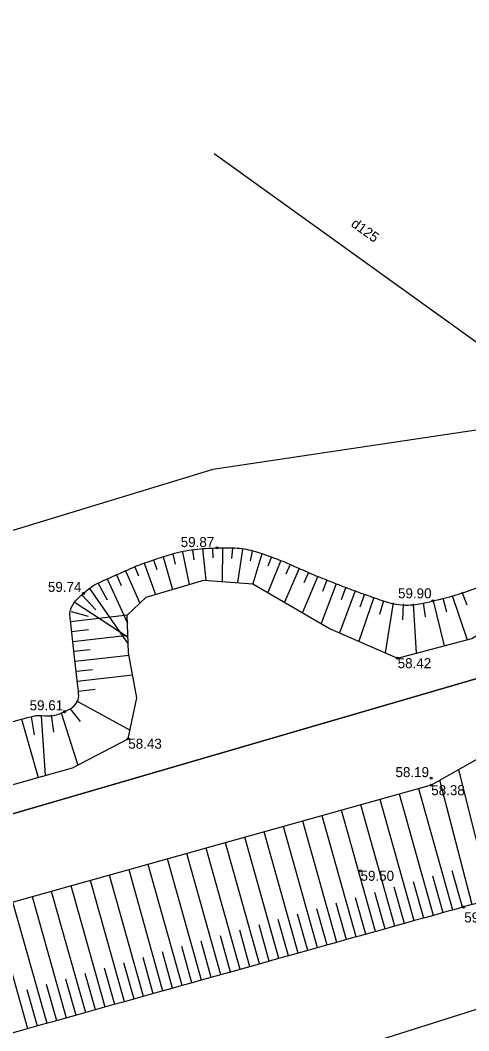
# Model space of a CAD drawing. Extents: x 616607 to 617499, y 408385 to 409695.
# Drawn here: x 616915.2 to 616937.6, y 408564.5 to 408614.9 of the extents above; entities that cross this region are included whole.
import ezdxf

# ---------------------------------------------------------------- set-up
doc = ezdxf.new("R2010")
doc.units = 0
for name, color, linetype in [('DREN_VADP_####_####_#', 7, 'Continuous'), ('DREN_VADP_####_TKST_#', 7, 'Continuous'), ('HIDG_GRAV_####_####_#', 7, 'Continuous'), ('RAMI_UZMR_####_####_#', 7, 'Continuous'), ('RELJ_AATZ_####_TKST_#', 7, 'Continuous'), ('RELJ_ELEM_####_####_#', 7, 'Continuous'), ('RELJ_NOGA_####_####_#', 7, 'Continuous'), ('ROBZ_IERR_####_####_#', 7, 'Continuous'), ('ROBZ_UZMR_####_####_#', 7, 'Continuous')]:
    doc.layers.add(name, color=color, linetype=linetype)

# ---------------------------------------------------------------- blocks, each defined once
blk = doc.blocks.new('PKT')
at = {"layer": 'RELJ_ELEM_####_####_#'}
blk.add_circle((0, 0), 0.05, dxfattribs=at)

msp = doc.modelspace()

# ---------------------------------------------------------------- linework, layer by layer
at = {"layer": 'DREN_VADP_####_####_#'}
msp.add_lwpolyline([(616944.351, 408594.236), (616924.897, 408608.204)], dxfattribs=at)
at = {"layer": 'HIDG_GRAV_####_####_#'}
for points in [[(616768.796, 408535.775), (616917.84, 408577.602), (616920.619, 408579.054), (616921.042, 408581.087), (616920.637, 408583.341), (616920.568, 408585.209), (616921.519, 408586.112), (616924.38, 408586.959), (616926.829, 408586.782), (616930.695, 408584.537), (616934.052, 408583.069), (616937.754, 408584.05), (616942.21, 408586.817), (616945.351, 408589.192), (616956.708, 408604.801)], [(616957.621, 408604.01), (616947.332, 408588.16), (616947.6, 408585.931), (616945.208, 408582.089), (616935.727, 408576.737), (616858.974, 408555.268)]]:
    msp.add_lwpolyline(points, dxfattribs=at)
at = {"layer": 'RAMI_UZMR_####_####_#'}
for points in [[(617191.828, 409115.62), (617145.545, 408952.8), (617072.809, 408766.141), (616965.332, 408652.076), (616939.432, 408594.661), (616924.839, 408592.467), (616706.433, 408526.081), (616666.426, 408467.691)], [(616666.426, 408467.691), (616675.529, 408457.882), (616687.228, 408463.356), (616723.888, 408465.775), (616753.554, 408507.232), (616948.282, 408568.831), (616981.528, 408608.531), (617014.563, 408672.892), (617101.571, 408748.246), (617213.472, 409074.039)]]:
    msp.add_lwpolyline(points, dxfattribs=at)
at = {"layer": 'RELJ_NOGA_####_####_#'}
for p, q in [((616924.315, 408588.513), (616924.48, 408586.952)), ((616924.315, 408588.513), (616924.316, 408588.512)), ((616924.814, 408588.555), (616924.841, 408588.065)), ((616924.814, 408588.555), (616924.814, 408588.555)), ((616925.313, 408588.569), (616925.3, 408586.893)), ((616925.313, 408588.569), (616925.313, 408588.568)), ((616925.813, 408588.548), (616925.774, 408588.043)), ((616925.813, 408588.548), (616925.813, 408588.548)), ((616926.31, 408588.492), (616926.073, 408586.837)), ((616926.31, 408588.492), (616926.309, 408588.491)), ((616921.88, 408587.968), (616922.039, 408587.49)), ((616921.88, 408587.968), (616921.88, 408587.968)), ((616922.358, 408588.116), (616922.824, 408586.499)), ((616922.358, 408588.116), (616922.358, 408588.115)), ((616922.841, 408588.246), (616922.962, 408587.759)), ((616922.841, 408588.246), (616922.841, 408588.246)), ((616923.328, 408588.357), (616923.653, 408586.744)), ((616923.328, 408588.357), (616923.328, 408588.356)), ((616923.82, 408588.447), (616923.895, 408587.973)), ((616923.82, 408588.447), (616923.82, 408588.446)), ((616926.801, 408588.401), (616926.694, 408587.923)), ((616926.801, 408588.401), (616926.801, 408588.4)), ((616927.285, 408588.274), (616926.833, 408586.78)), ((616927.285, 408588.274), (616927.284, 408588.273)), ((616927.758, 408588.114), (616927.584, 408587.654)), ((616927.758, 408588.114), (616927.758, 408588.113)), ((616920.943, 408587.621), (616921.127, 408587.171)), ((616920.943, 408587.621), (616920.943, 408587.62)), ((616921.408, 408587.803), (616921.983, 408586.25)), ((616921.408, 408587.803), (616921.409, 408587.802)), ((616928.224, 408587.931), (616927.577, 408586.348)), ((616928.224, 408587.931), (616928.223, 408587.93)), ((616929.145, 408587.542), (616928.417, 408585.86)), ((616928.685, 408587.739), (616928.478, 408587.249)), ((616928.685, 408587.739), (616928.685, 408587.739)), ((616929.145, 408587.542), (616929.145, 408587.541)), ((616919.57, 408587.016), (616920.583, 408584.814)), ((616919.57, 408587.016), (616919.571, 408587.015)), ((616920.026, 408587.221), (616920.265, 408586.69)), ((616920.026, 408587.221), (616920.026, 408587.221)), ((616920.483, 408587.425), (616921.194, 408585.804)), ((616920.483, 408587.425), (616920.483, 408587.424)), ((616930.064, 408587.149), (616929.312, 408585.34)), ((616929.604, 408587.344), (616929.38, 408586.822)), ((616929.604, 408587.344), (616929.604, 408587.344)), ((616930.064, 408587.149), (616930.064, 408587.148)), ((616930.528, 408586.961), (616930.303, 408586.394)), ((616930.528, 408586.961), (616930.528, 408586.961)), ((616918.694, 408586.536), (616920.621, 408583.766)), ((616918.694, 408586.536), (616918.695, 408586.536)), ((616919.122, 408586.795), (616919.568, 408585.969)), ((616919.122, 408586.795), (616919.122, 408586.795)), ((616930.994, 408586.78), (616930.234, 408584.805)), ((616930.994, 408586.78), (616930.993, 408586.779)), ((616931.461, 408586.601), (616931.229, 408585.984)), ((616931.461, 408586.601), (616931.461, 408586.601)), ((616918.302, 408586.227), (616918.998, 408585.48)), ((616918.302, 408586.227), (616918.302, 408586.226)), ((616931.929, 408586.427), (616931.158, 408584.335)), ((616931.929, 408586.427), (616931.929, 408586.426)), ((616932.87, 408586.088), (616932.109, 408583.919)), ((616932.399, 408586.256), (616932.169, 408585.617)), ((616932.399, 408586.256), (616932.399, 408586.255)), ((616932.87, 408586.088), (616932.87, 408586.087)), ((616936.3, 408586.053), (616936.493, 408585.387)), ((616936.3, 408586.053), (616936.3, 408586.053)), ((616936.778, 408586.201), (616937.512, 408583.986)), ((616936.778, 408586.201), (616936.778, 408586.2)), ((616937.248, 408586.37), (616937.495, 408585.733)), ((616937.248, 408586.37), (616937.248, 408586.37)), ((616917.978, 408585.848), (616920.608, 408584.12)), ((616917.978, 408585.848), (616917.979, 408585.847)), ((616933.344, 408585.93), (616933.147, 408585.25)), ((616933.344, 408585.93), (616933.344, 408585.929)), ((616933.832, 408585.823), (616933.429, 408583.341)), ((616933.832, 408585.823), (616933.832, 408585.822)), ((616934.33, 408585.774), (616934.296, 408584.975)), ((616934.33, 408585.774), (616934.33, 408585.773)), ((616934.83, 408585.776), (616934.968, 408583.311)), ((616934.83, 408585.776), (616934.83, 408585.775)), ((616935.327, 408585.827), (616935.431, 408585.129)), ((616935.327, 408585.827), (616935.327, 408585.827)), ((616935.817, 408585.924), (616936.374, 408583.684)), ((616935.817, 408585.924), (616935.817, 408585.923)), ((616917.736, 408584.901), (616920.587, 408585.226)), ((616917.767, 408585.397), (616918.614, 408585.155)), ((616917.767, 408585.397), (616917.767, 408585.396)), ((616917.736, 408584.901), (616917.737, 408584.901)), ((616917.793, 408584.404), (616918.631, 408584.5)), ((616917.793, 408584.404), (616917.793, 408584.404)), ((616917.85, 408583.908), (616920.604, 408584.222)), ((616917.85, 408583.908), (616917.851, 408583.908)), ((616917.906, 408583.411), (616918.721, 408583.504)), ((616917.906, 408583.411), (616917.907, 408583.411)), ((616917.963, 408582.914), (616920.658, 408583.221)), ((616917.963, 408582.914), (616917.964, 408582.914)), ((616918.02, 408582.417), (616918.838, 408582.511)), ((616918.02, 408582.417), (616918.02, 408582.417)), ((616918.076, 408581.921), (616920.836, 408582.234)), ((616918.076, 408581.921), (616918.077, 408581.921)), ((616918.133, 408581.424), (616918.97, 408581.519)), ((616918.133, 408581.424), (616918.133, 408581.424)), ((616918.036, 408580.942), (616920.708, 408579.481)), ((616918.036, 408580.942), (616918.037, 408580.942)), ((616917.712, 408580.565), (616918.214, 408579.918)), ((616917.712, 408580.565), (616917.713, 408580.565)), ((616915.3, 408580.032), (616916.124, 408577.12)), ((616915.3, 408580.032), (616915.3, 408580.031)), ((616915.785, 408580.15), (616915.919, 408579.25)), ((616915.785, 408580.15), (616915.785, 408580.15)), ((616916.283, 408580.198), (616916.473, 408577.218)), ((616916.283, 408580.198), (616916.283, 408580.197)), ((616916.781, 408580.237), (616916.884, 408579.386)), ((616916.781, 408580.237), (616916.781, 408580.237)), ((616917.27, 408580.338), (616918.097, 408577.736)), ((616917.27, 408580.338), (616917.27, 408580.338)), ((616938.73, 408571.022), (616937.096, 408577.51)), ((616937.76, 408570.779), (616936.159, 408576.981)), ((616936.796, 408570.514), (616935.108, 408576.563)), ((616934.87, 408569.977), (616933.181, 408576.025)), ((616935.833, 408570.246), (616934.144, 408576.294)), ((616932.943, 408569.439), (616931.254, 408575.486)), ((616933.906, 408569.708), (616932.218, 408575.755)), ((616931.017, 408568.901), (616929.328, 408574.947)), ((616931.98, 408569.17), (616930.291, 408575.216)), ((616929.091, 408568.362), (616927.401, 408574.408)), ((616930.054, 408568.632), (616928.364, 408574.677)), ((616927.165, 408567.824), (616925.473, 408573.869)), ((616928.128, 408568.093), (616926.438, 408574.139)), ((616926.202, 408567.554), (616924.51, 408573.599)), ((616924.276, 408567.015), (616922.582, 408573.06)), ((616925.239, 408567.285), (616923.547, 408573.33)), ((616922.35, 408566.476), (616920.656, 408572.521)), ((616923.313, 408566.745), (616921.619, 408572.791)), ((616937.278, 408570.649), (616936.771, 408572.464)), ((616920.424, 408565.935), (616918.728, 408571.982)), ((616921.387, 408566.206), (616919.691, 408572.251)), ((616935.351, 408570.111), (616934.845, 408571.926)), ((616936.314, 408570.38), (616935.808, 408572.195)), ((616918.499, 408565.395), (616916.799, 408571.443)), ((616919.461, 408565.665), (616917.765, 408571.713)), ((616933.425, 408569.573), (616932.918, 408571.387)), ((616934.388, 408569.842), (616933.882, 408571.657)), ((616916.573, 408564.854), (616914.871, 408570.903)), ((616917.536, 408565.124), (616915.836, 408571.173)), ((616931.499, 408569.035), (616930.992, 408570.849)), ((616932.462, 408569.304), (616931.955, 408571.118)), ((616915.611, 408564.583), (616913.908, 408570.634)), ((616930.535, 408568.766), (616930.029, 408570.58)), ((616936.314, 408570.38), (616936.314, 408570.38)), ((616936.796, 408570.514), (616936.796, 408570.515)), ((616937.278, 408570.649), (616937.278, 408570.649)), ((616928.609, 408568.228), (616928.102, 408570.041)), ((616929.572, 408568.497), (616929.065, 408570.311)), ((616934.388, 408569.842), (616934.388, 408569.843)), ((616934.87, 408569.977), (616934.869, 408569.978)), ((616935.351, 408570.111), (616935.351, 408570.111)), ((616935.833, 408570.246), (616935.833, 408570.246)), ((616926.683, 408567.689), (616926.176, 408569.503)), ((616927.646, 408567.959), (616927.139, 408569.772)), ((616932.943, 408569.439), (616932.943, 408569.44)), ((616933.425, 408569.573), (616933.425, 408569.574)), ((616933.906, 408569.708), (616933.906, 408569.709)), ((616924.757, 408567.15), (616924.25, 408568.964)), ((616925.72, 408567.42), (616925.213, 408569.233)), ((616931.017, 408568.901), (616931.017, 408568.902)), ((616931.499, 408569.035), (616931.499, 408569.036)), ((616931.98, 408569.17), (616931.98, 408569.171)), ((616932.462, 408569.304), (616932.462, 408569.305)), ((616922.831, 408566.61), (616922.323, 408568.424)), ((616923.794, 408566.88), (616923.286, 408568.694)), ((616929.091, 408568.362), (616929.091, 408568.363)), ((616929.572, 408568.497), (616929.572, 408568.497)), ((616930.054, 408568.632), (616930.054, 408568.633)), ((616930.535, 408568.766), (616930.535, 408568.767)), ((616920.906, 408566.07), (616920.397, 408567.884)), ((616921.869, 408566.341), (616921.36, 408568.154)), ((616927.165, 408567.824), (616927.164, 408567.825)), ((616927.646, 408567.959), (616927.646, 408567.959)), ((616928.128, 408568.093), (616928.128, 408568.094)), ((616928.609, 408568.228), (616928.609, 408568.228)), ((616918.98, 408565.53), (616918.47, 408567.344)), ((616919.943, 408565.8), (616919.434, 408567.614)), ((616925.72, 408567.42), (616925.72, 408567.42)), ((616926.202, 408567.554), (616926.201, 408567.555)), ((616926.683, 408567.689), (616926.683, 408567.689)), ((616917.055, 408564.989), (616916.545, 408566.804)), ((616918.017, 408565.26), (616917.508, 408567.074)), ((616923.794, 408566.88), (616923.794, 408566.881)), ((616924.276, 408567.015), (616924.276, 408567.016)), ((616924.757, 408567.15), (616924.757, 408567.15)), ((616925.239, 408567.285), (616925.238, 408567.286)), ((616916.092, 408564.718), (616915.581, 408566.533)), ((616921.869, 408566.341), (616921.868, 408566.341)), ((616922.35, 408566.476), (616922.35, 408566.477)), ((616922.831, 408566.61), (616922.831, 408566.611)), ((616923.313, 408566.745), (616923.313, 408566.746)), ((616919.943, 408565.8), (616919.943, 408565.801)), ((616920.424, 408565.935), (616920.424, 408565.936)), ((616920.906, 408566.07), (616920.906, 408566.071)), ((616921.387, 408566.206), (616921.387, 408566.207)), ((616918.499, 408565.395), (616918.498, 408565.396)), ((616918.98, 408565.53), (616918.98, 408565.53)), ((616919.461, 408565.665), (616919.461, 408565.666)), ((616916.573, 408564.854), (616916.573, 408564.855)), ((616917.055, 408564.989), (616917.055, 408564.989)), ((616917.536, 408565.124), (616917.536, 408565.125)), ((616918.017, 408565.26), (616918.017, 408565.26)), ((616915.611, 408564.583), (616915.61, 408564.584)), ((616916.092, 408564.718), (616916.092, 408564.718))]:
    msp.add_line(p, q, dxfattribs=at)
msp.add_open_spline([(616975.731, 408606.41), (616971.71, 408604.144), (616967.689, 408601.878), (616963.668, 408599.612), (616962.341, 408598.864), (616961.192, 408597.791), (616960.311, 408596.511), (616959.39, 408595.173), (616958.675, 408593.776), (616958.002, 408592.329), (616957.302, 408590.825), (616956.736, 408589.272), (616956.015, 408587.778), (616955.313, 408586.324), (616954.582, 408584.882), (616953.626, 408583.572), (616952.496, 408582.025), (616951.261, 408580.593), (616950.022, 408579.143), (616948.785, 408577.695), (616947.537, 408576.278), (616946.22, 408574.895), (616945.626, 408574.271), (616944.957, 408573.742), (616944.225, 408573.278), (616943.451, 408572.788), (616942.648, 408572.387), (616941.804, 408572.051), (616941, 408571.73), (616940.2, 408571.414), (616939.368, 408571.187), (616938.69, 408571.002), (616938.005, 408570.852), (616937.329, 408570.663), (616918.615, 408565.441), (616899.903, 408560.204), (616881.253, 408554.75), (616874.57, 408552.796), (616867.991, 408550.484), (616861.269, 408548.669), (616855.483, 408547.106), (616849.688, 408545.577), (616843.9, 408544.023), (616838.111, 408542.469), (616832.323, 408540.916), (616826.537, 408539.352), (616816.497, 408536.637), (616806.51, 408533.737), (616796.541, 408530.774), (616791.553, 408529.292), (616786.584, 408527.751), (616781.609, 408526.226), (616776.622, 408524.697), (616771.656, 408523.11), (616766.688, 408521.515), (616762.607, 408520.204), (616758.677, 408518.521), (616754.775, 408516.687), (616750.921, 408514.875), (616747.341, 408512.653), (616743.915, 408510.109), (616740.341, 408507.454), (616736.942, 408504.677), (616733.801, 408501.555), (616732.131, 408499.895), (616730.49, 408498.223), (616728.926, 408496.468), (616728.114, 408495.556), (616727.318, 408494.632), (616726.518, 408493.709), (616725.695, 408492.76), (616724.91, 408491.864), (616724.122, 408490.803), (616723.665, 408490.187), (616723.18, 408489.459), (616723.332, 408488.764), (616723.537, 408487.829), (616723.949, 408486.896), (616724.213, 408485.954), (616724.975, 408483.236), (616725.742, 408480.486), (616726.381, 408477.738), (616726.631, 408476.667), (616726.554, 408475.507), (616726.221, 408474.429), (616726.043, 408473.855), (616725.77, 408473.346), (616725.415, 408472.86), (616725.226, 408472.602), (616725.032, 408472.37), (616724.813, 408472.14), (616724.582, 408471.898), (616724.347, 408471.683), (616724.071, 408471.48), (616723.783, 408471.268), (616723.475, 408471.091), (616723.13, 408471.039), (616722.812, 408470.991), (616722.494, 408470.986), (616722.176, 408470.982), (616721.543, 408470.975), (616720.901, 408471.154), (616720.278, 408471.02), (616716.569, 408470.219), (616712.93, 408469.339), (616709.261, 408468.478), (616707.424, 408468.047), (616705.589, 408467.613), (616703.751, 408467.182), (616701.927, 408466.754), (616700.076, 408466.424), (616698.236, 408466.115), (616695.42, 408465.64), (616692.315, 408465.565), (616689.691, 408467.073), (616684.319, 408470.158), (616679.892, 408473.486), (616675.008, 408476.777), (616674.831, 408476.896), (616674.652, 408477.012), (616674.483, 408477.14), (616674.175, 408477.376), (616674.46, 408477.978), (616674.696, 408478.288), (616675.427, 408479.251), (616676.165, 408480.2), (616676.939, 408481.135), (616677.893, 408482.289), (616678.812, 408483.429), (616679.848, 408484.532), (616681.078, 408485.839), (616682.698, 408486.726), (616684.412, 408487.237), (616686.183, 408487.764), (616687.958, 408488.143), (616689.768, 408488.401), (616691.642, 408488.668), (616693.528, 408488.826), (616695.398, 408489.116), (616696.323, 408489.26), (616697.239, 408489.444), (616698.155, 408489.647), (616699.054, 408489.848), (616699.912, 408490.166), (616700.785, 408490.476), (616703.122, 408491.305), (616705.613, 408491.942), (616707.248, 408494.043), (616707.429, 408494.275), (616707.474, 408494.537), (616707.552, 408494.798), (616707.628, 408495.051), (616707.711, 408495.3), (616707.761, 408495.559), (616707.86, 408496.068), (616707.943, 408496.577), (616707.977, 408497.092), (616708.044, 408498.12), (616708.108, 408499.147), (616708.168, 408500.175), (616708.254, 408501.63), (616708.34, 408503.085), (616708.414, 408504.54), (616708.488, 408505.998), (616708.403, 408507.461), (616708.436, 408508.92), (616708.468, 408510.38), (616708.539, 408511.837), (616708.686, 408513.293), (616708.76, 408514.026), (616708.887, 408514.749), (616709.039, 408515.47), (616709.116, 408515.834), (616709.208, 408516.193), (616709.297, 408516.554), (616709.387, 408516.92), (616709.487, 408517.278), (616709.619, 408517.635), (616710.681, 408520.51), (616712.959, 408522.898), (616715.736, 408524.335), (616718.688, 408525.863), (616721.668, 408526.887), (616724.792, 408527.643), (616730.078, 408528.922), (616735.359, 408530.207), (616740.655, 408531.436), (616749.901, 408533.581), (616759.244, 408535.317), (616768.413, 408537.779), (616798.7, 408545.91), (616828.618, 408555.288), (616858.746, 408563.964), (616877.646, 408569.406), (616896.581, 408574.731), (616915.501, 408580.089), (616916.131, 408580.267), (616916.803, 408580.127), (616917.44, 408580.402), (616917.832, 408580.571), (616918.181, 408580.992), (616918.136, 408581.394), (616918.071, 408581.969), (616918.005, 408582.544), (616917.94, 408583.119), (616917.87, 408583.733), (616917.799, 408584.347), (616917.73, 408584.96), (616917.674, 408585.454), (616917.97, 408585.948), (616918.384, 408586.3), (616918.906, 408586.742), (616919.445, 408586.959), (616920.02, 408587.218), (616920.568, 408587.465), (616921.093, 408587.698), (616921.676, 408587.899), (616922.792, 408588.284), (616923.918, 408588.529), (616925.044, 408588.565), (616925.938, 408588.594), (616926.854, 408588.454), (616927.734, 408588.123), (616928.677, 408587.768), (616929.526, 408587.359), (616930.432, 408586.999), (616931.324, 408586.645), (616932.223, 408586.313), (616933.127, 408585.998), (616933.97, 408585.704), (616934.935, 408585.706), (616935.807, 408585.922), (616937.564, 408586.355), (616939.443, 408587.201), (616940.422, 408588.724), (616944.438, 408594.972), (616948.27, 408601.228), (616952.11, 408607.531)], degree=3, dxfattribs=at)
at = {"layer": 'ROBZ_IERR_####_####_#'}
msp.add_lwpolyline([(617055.284, 408797.783), (617087.528, 408757.04), (616999.181, 408676.019), (616968.565, 408608.405), (616958.517, 408604.593), (616940.576, 408582.801), (616889.795, 408568.012), (616805.459, 408543.657), (616730.494, 408522.344), (616717.135, 408556.579)], dxfattribs=at)
at = {"layer": 'ROBZ_UZMR_####_####_#'}
msp.add_lwpolyline([(616704.998, 408460.626), (616695.309, 408466.84), (616688.046, 408471.498), (616708.653, 408488.203), (616730.494, 408522.344), (616805.459, 408543.657), (616889.795, 408568.012), (616940.576, 408582.801), (616958.517, 408604.593), (616968.565, 408608.405), (616974.837, 408605.827), (616993.227, 408598.268)], dxfattribs=at)

# ---------------------------------------------------------------- block references
at = {"layer": 'RELJ_ELEM_####_####_#'}
for p in [(616925.044, 408588.565), (616918.384, 408586.3), (616935.807, 408585.922), (616934.052, 408583.069), (616917.44, 408580.402), (616920.619, 408579.054), (616935.724, 408577.089), (616935.727, 408576.737), (616932.201, 408572.472), (616937.329, 408570.663)]:
    msp.add_blockref('PKT', p, dxfattribs=at)

# ---------------------------------------------------------------- texts
at = {"layer": 'DREN_VADP_####_TKST_#'}
msp.add_text('d125', height=0.5, rotation=324.3222, dxfattribs=at).set_placement((616931.685, 408604.632))
at = {"layer": 'RELJ_AATZ_####_TKST_#'}
for s, p in [('59.87', (616923.234, 408588.608)), ('59.74', (616916.611, 408586.373)), ('59.90', (616934.071, 408586.052)), ('58.42', (616934.052, 408582.569)), ('59.61', (616915.699, 408580.47)), ('58.43', (616920.619, 408578.554)), ('58.19', (616933.944, 408577.139)), ('58.38', (616935.727, 408576.237)), ('59.50', (616932.201, 408571.972)), ('59.86', (616937.373, 408569.895))]:
    msp.add_text(s, height=0.5, dxfattribs=at).set_placement(p)

doc.saveas('drawing.dxf')
